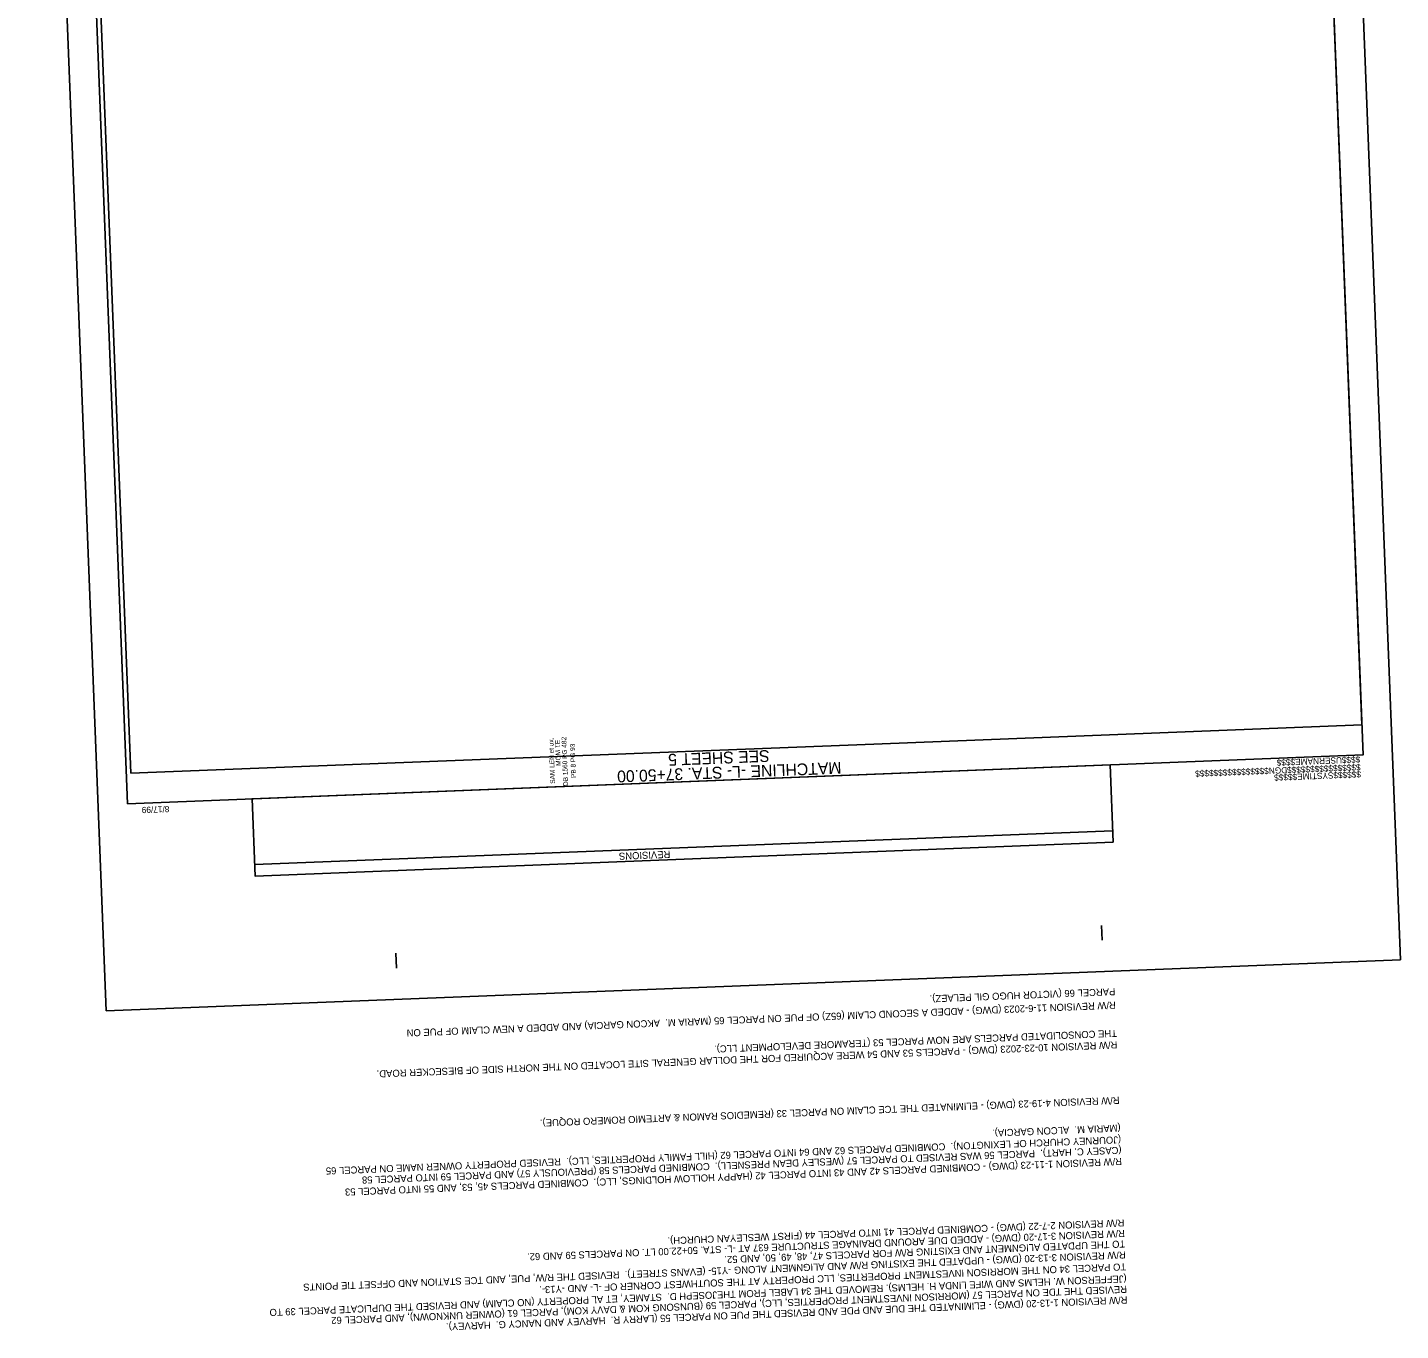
# Model space of a CAD drawing. Extents: x 1627804 to 1628970, y 763730 to 765944.
# Drawn here: x 1627804 to 1628970, y 763730 to 764837 of the extents above; entities that cross this region are included whole.
import ezdxf

# ---------------------------------------------------------------- set-up
doc = ezdxf.new("R2010")
doc.units = 0
for name, color, linetype in [('Exist Other Culture Sign Post CELL', 7, 'Continuous'), ('Exist Right of Way Control of Access Line', 7, 'Continuous'), ('Exist Right of Way Easement Line', 7, 'Continuous'), ('Exist Right of Way Monument Text', 7, 'Continuous'), ('Exist Roads Concrete Median Barrier', 7, 'Continuous'), ('Exist Roads EOT', 7, 'Continuous'), ('Exist Structure Major Deck Tunnel Box Culvert', 7, 'Continuous'), ('Exist Utilities Gas UG Line', 7, 'Continuous'), ('Exist Utilities Other Unknown UG SUE Text', 7, 'Continuous')]:
    doc.layers.add(name, color=color, linetype=linetype)

msp = doc.modelspace()

# ---------------------------------------------------------------- linework, layer by layer
at = {"layer": 'Exist Right of Way Control of Access Line'}
msp.add_line((1628725.2, 764154.9), (1627996.6, 764126.2), dxfattribs=at)
msp.add_lwpolyline([(1628725.6, 764145.1), (1627997, 764116.4), (1627994.4, 764182.1), (1628723, 764210.8)], close=True, dxfattribs=at)
at = {"layer": 'Exist Right of Way Monument Text'}
for p, q in [((1628938.4, 764204.9), (1628938.4, 764204.9)), ((1628938.4, 764204.9), (1628938.4, 764204.9)), ((1628938.4, 764204.9), (1628938.4, 764204.9)), ((1628938.4, 764204.9), (1628938.4, 764204.9)), ((1628938.4, 764204.9), (1628938.4, 764204.9)), ((1628716.4, 764061.9), (1628715.9, 764074.4)), ((1628116.9, 764038.3), (1628116.4, 764050.8))]:
    msp.add_line(p, q, dxfattribs=at)
msp.add_lwpolyline([(1627829.6, 765676.7), (1627888.7, 764177.9), (1628937.9, 764219.3), (1628878.8, 765718.1)], close=True, dxfattribs=at)
at = {"layer": 'Exist Roads EOT'}
msp.add_line((1628522.5, 764228.5), (1628282.7, 764219.1), dxfattribs=at)
at = {"layer": 'Exist Structure Major Deck Tunnel Box Culvert'}
msp.add_lwpolyline([(1628282.7, 764219.1), (1628522.5, 764228.5), (1628936.9, 764244.9), (1628878.8, 765718.1), (1628011.8, 765683.9), (1628019.8, 765481.2), (1628020.3, 765468.3), (1627907.4, 765463.8), (1627915.4, 765262.8), (1627849.8, 765260.2), (1627891.5, 764203.9)], close=True, dxfattribs=at)
at = {"layer": 'Exist Utilities Gas UG Line'}
msp.add_lwpolyline([(1628969.7, 764045.4), (1628902.8, 765744.1), (1627803.6, 765700.7), (1627870.6, 764002.1)], close=True, dxfattribs=at)
at = {"layer": 'Exist Utilities Other Unknown UG SUE Text'}
msp.add_line((1628937.9, 764219.3), (1628937.9, 764219.3), dxfattribs=at)

# ---------------------------------------------------------------- texts
at = {"layer": 'Exist Other Culture Sign Post CELL'}
for s, p in [('SAM LEN et ux,', (1628251.7, 764194.9)), ('MOM TE', (1628256.5, 764210.1)), ('DB 1560 PG 482', (1628262.8, 764193)), ('PB 8 PG 93', (1628269.5, 764199.8))]:
    msp.add_text(s, height=4, rotation=92.2582, dxfattribs=at).set_placement(p)
at = {"layer": 'Exist Right of Way Control of Access Line'}
msp.add_text('REVISIONS', height=6, rotation=182.2582, dxfattribs=at).set_placement((1628349.5, 764137.9))
at = {"layer": 'Exist Right of Way Easement Line'}
for s, p in [('PARCEL 66 (VICTOR HUGO GIL PELAEZ).', (1628727.4, 764021.3)), ('R/W REVISION 11-6-2023 (DWG) - ADDED A SECOND CLAIM (65Z) OF PUE ON PARCEL 65 (MARIA M.  AKCON GARCIA) AND ADDED A NEW CLAIM OF PUE ON ', (1628727.8, 764009.8)), ('THE CONSOLIDATED PARCELS ARE NOW PARCEL 53 (TERAMORE DEVELOPMENT LLC).', (1628728.8, 763985.9)), ('R/W REVISION 10-23-2023 (DWG) - PARCELS 53 AND 54 WERE ACQUIRED FOR THE DOLLAR GENERAL SITE LOCATED ON THE NORTH SIDE OF BIESECKER ROAD. ', (1628729.1, 763976.1)), ('R/W REVISION 4-19-23 (DWG) - ELIMINATED THE TCE CLAIM ON PARCEL 33 (REMEDIOS RAMON & ARTEMIO ROMERO ROQUE). ', (1628731, 763929)), ('(JOURNEY CHURCH OF LEXINGTON).  COMBINED PARCELS 62 AND 64 INTO PARCEL 62 (HILL FAMILY PROPERTIES, LLC).  REVISED PROPERTY OWNER NAME ON PARCEL 65 ', (1628732.3, 763895.5)), ('(MARIA M.  ALCON GARCIA).', (1628731.9, 763905.4)), ('(CASEY C. HART).  PARCEL 56 WAS REVISED TO PARCEL 57 (WESLEY DEAN PRESNELL).  COMBINED PARCELS 58 (PREVIOUSLY 57) AND PARCEL 59 INTO PARCEL 58 ', (1628732.7, 763886.6)), ('R/W REVISION 1-11-23 (DWG) - COMBINED PARCELS 42 AND 43 INTO PARCEL 42 (HAPPY HOLLOW HOLDINGS, LLC).  COMBINED PARCELS 45, 53, AND 55 INTO PARCEL 53 ', (1628733, 763877)), ('R/W REVISION 3-17-20 (DWG) - ADDED DUE AROUND DRAINAGE STRUCTURE 637 AT -L- STA. 50+22.00 LT. ON PARCELS 59 AND 62.', (1628735.5, 763815.9)), ('R/W REVISION 2-7-22 (DWG) - COMBINED PARCEL 41 INTO PARCEL 44 (FIRST WESLEYAN CHURCH).', (1628735.1, 763824.9)), ('TO THE UPDATED ALIGNMENT AND EXISTING R/W FOR PARCELS 47, 48, 49, 50, AND 52.', (1628735.8, 763807)), ('R/W REVISION 3-13-20 (DWG) - UPDATED THE EXISTING R/W AND ALIGNMENT ALONG -Y15- (EVANS STREET).  REVISED THE R/W, PUE, AND TCE STATION AND OFFSET TIE POINTS ', (1628736.2, 763797.7)), ('TO PARCEL 34 ON THE MORRISON INVESTMENT PROPERTIES, LLC PROPERTY AT THE SOUTHWEST CORNER OF -L- AND -Y13-. ', (1628736.6, 763787.6)), ('(JEFFERSON W. HELMS AND WIFE LINDA H. HELMS). REMOVED THE 34 LABEL FROM THEJOSEPH D.  STAMEY, ET AL PROPERTY (NO CLAIM) AND REVISED THE DUPLICATE PARCEL 39 TO', (1628737, 763777.4)), ('REVISED THE TDE ON PARCEL 57 (MORRISON INVESTMENT PROPERTIES, LLC), PARCEL 59 (BUNSONG KOM & DAVY KOM), PARCEL 61 (OWNER UNKNOWN), AND PARCEL 62', (1628737.3, 763768.5)), ('R/W REVISION 1-13-20 (DWG) - ELIMINATED THE DUE AND PDE AND REVISED THE PUE ON PARCEL 55 (LARRY R.  HARVEY AND NANCY G.  HARVEY).', (1628737.7, 763759.4))]:
    msp.add_text(s, height=6, rotation=182.2582, dxfattribs=at).set_placement(p)
at = {"layer": 'Exist Right of Way Monument Text'}
msp.add_text('8/17/99', height=5.25, rotation=182.2582, dxfattribs=at).set_placement((1627924, 764176))
at = {"layer": 'Exist Roads Concrete Median Barrier'}
for s, p in [('SEE SHEET 5', (1628433.7, 764223.5)), ('MATCHLINE -L- STA. 37+50.00', (1628494.7, 764213.4))]:
    msp.add_text(s, height=10, rotation=182.2582, dxfattribs=at).set_placement(p)
at = {"layer": 'Exist Utilities Other Unknown UG SUE Text'}
for s, p in [('$$$$$$$$$$$$$$$$DGN$$$$$$$$$$$$$$$$', (1628935.8, 764211.5)), ('$$$$USERNAME$$$$', (1628935.5, 764218.1)), ('$$$$$$SYSTIME$$$$$', (1628936.1, 764205.5))]:
    msp.add_text(s, height=5.25, rotation=182.2582, dxfattribs=at).set_placement(p)

doc.saveas('drawing.dxf')
